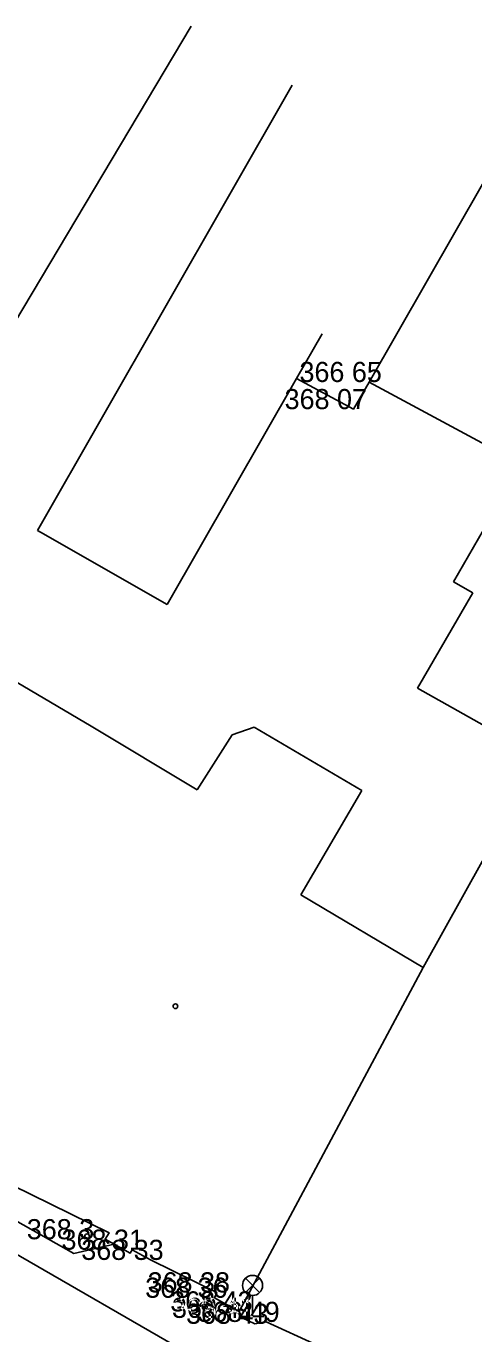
# Model space of a CAD drawing. Extents: x -688316 to -688024, y -973785 to -973591.
# Drawn here: x -688125.39 to -688108.72, y -973639.59 to -973590.87 of the extents above; entities that cross this region are included whole.
import ezdxf

# ---------------------------------------------------------------- set-up
doc = ezdxf.new("R2010")
doc.units = 0
for name, color, linetype in [('Vrstva 10', 7, 'Continuous'), ('Vrstva 3', 7, 'Continuous'), ('Vrstva 33', 7, 'Continuous'), ('Vrstva 5', 7, 'Continuous'), ('Vrstva 58', 7, 'Continuous'), ('Vrstva 7', 7, 'Continuous')]:
    doc.layers.add(name, color=color, linetype=linetype)

# ---------------------------------------------------------------- blocks, each defined once
blk = doc.blocks.new('B_NESP')
at = {"layer": 'Vrstva 58'}
blk.add_circle((0, 0), 0.875, dxfattribs=at)
blk = doc.blocks.new('LAO')
at = {"layer": 'Vrstva 33'}
for p, q in [((-2.65, 14.16), (2.65, 8.85)), ((-2.65, 8.85), (2.65, 14.16)), ((0, 0), (0, 7.75))]:
    blk.add_line(p, q, dxfattribs=at)
blk.add_circle((0, 11.5), 3.75, dxfattribs=at)

msp = doc.modelspace()

# ---------------------------------------------------------------- linework, layer by layer
at = {"layer": 'Vrstva 10'}
msp.add_line((-688128.13, -973635.26), (-688116.85, -973641.76), dxfattribs=at)
at = {"layer": 'Vrstva 5'}
for p, q in [((-688119.25, -973590.87), (-688128.07, -973605.69)), ((-688124.97, -973609.66), (-688115.48, -973593.07)), ((-688124.86, -973609.72), (-688124.97, -973609.66)), ((-688120.14, -973612.42), (-688124.86, -973609.72)), ((-688128.71, -973613.57), (-688122.97, -973616.95)), ((-688122.97, -973616.95), (-688119.02, -973619.32)), ((-688117.72, -973617.27), (-688116.9, -973616.99)), ((-688116.9, -973616.99), (-688112.89, -973619.35)), ((-688119.02, -973619.32), (-688117.72, -973617.27)), ((-688110.61, -973625.94), (-688106.58, -973618.7)), ((-688112.89, -973619.35), (-688115.16, -973623.24)), ((-688115.16, -973623.24), (-688110.61, -973625.94)), ((-688117.46, -973638.76), (-688110.61, -973625.94))]:
    msp.add_line(p, q, dxfattribs=at)
for points in [[(-688105.15, -973591.1), (-688112.62, -973604.13), (-688113.2, -973605.14), (-688115.32, -973604)], [(-688114.37, -973602.34), (-688115.32, -973604), (-688120.14, -973612.42)], [(-688127.39, -973632.92), (-688126.75, -973633.39), (-688126.83, -973633.52), (-688126.17, -973633.9), (-688125.91, -973634.05), (-688122.3, -973635.83), (-688122.45, -973636.07), (-688122.11, -973636.25), (-688121.52, -973636.59), (-688121.44, -973636.46), (-688120.76, -973636.84), (-688118.29, -973638.05), (-688118.38, -973638.25), (-688117.46, -973638.76), (-688117.34, -973639), (-688116.87, -973639.22), (-688116.45, -973639.15), (-688114.55, -973640.02), (-688114.81, -973640.46), (-688114.6, -973640.52), (-688114.18, -973640.39)], [(-688126.17, -973633.9), (-688125.79, -973635.37), (-688123.61, -973636.6), (-688122.11, -973636.25)]]:
    msp.add_lwpolyline(points, dxfattribs=at)
at = {"layer": 'Vrstva 7'}
for p, q in [((-688106.28, -973607.55), (-688112.62, -973604.13)), ((-688109.47, -973611.58), (-688107.46, -973608.06)), ((-688108.76, -973611.98), (-688109.47, -973611.58)), ((-688110.82, -973615.54), (-688108.76, -973611.98)), ((-688106.23, -973618.12), (-688110.82, -973615.54))]:
    msp.add_line(p, q, dxfattribs=at)

# ---------------------------------------------------------------- block references
at = {"layer": 'Vrstva 33', "xscale": 0.1, "yscale": 0.10000000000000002}
msp.add_blockref('LAO', (-688116.96, -973638.94), dxfattribs=at)
at = {"layer": 'Vrstva 58', "xscale": 0.1, "yscale": 0.10000000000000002}
for p in [(-688119.83, -973627.39), (-688119.83, -973627.39), (-688119.83, -973627.39), (-688119.83, -973627.39), (-688123.12, -973635.96), (-688123.12, -973635.96), (-688123.12, -973635.96), (-688123.12, -973635.96)]:
    msp.add_blockref('B_NESP', p, dxfattribs=at)

# ---------------------------------------------------------------- texts
at = {"layer": 'Vrstva 3'}
for s, p in [('366 65 ', (-688115.212, -973604.13)), ('366 65 ', (-688115.212, -973604.13)), ('366 65 ', (-688115.212, -973604.13)), ('366 65 ', (-688115.212, -973604.13)), ('366 65 ', (-688115.212, -973604.13)), ('366 65 ', (-688115.212, -973604.13)), ('366 65 ', (-688115.212, -973604.13)), ('368 07 ', (-688115.766, -973605.14)), ('368 07 ', (-688115.766, -973605.14)), ('368 07 ', (-688115.766, -973605.14)), ('368 07 ', (-688115.766, -973605.14)), ('368 07 ', (-688115.766, -973605.14)), ('368 07 ', (-688115.766, -973605.14)), ('368 07 ', (-688115.766, -973605.14)), ('368 3  ', (-688125.367, -973636.07)), ('368 3  ', (-688125.367, -973636.07)), ('368 3  ', (-688125.367, -973636.07)), ('368 3  ', (-688125.367, -973636.07)), ('368 3  ', (-688125.367, -973636.07)), ('368 3  ', (-688125.367, -973636.07)), ('368 3  ', (-688125.367, -973636.07)), ('368 31 ', (-688124.073, -973636.46)), ('368 31 ', (-688124.073, -973636.46)), ('368 31 ', (-688124.073, -973636.46)), ('368 31 ', (-688124.073, -973636.46)), ('368 31 ', (-688124.073, -973636.46)), ('368 31 ', (-688124.073, -973636.46)), ('368 31 ', (-688124.073, -973636.46)), ('368 33 ', (-688123.338, -973636.84)), ('368 33 ', (-688123.338, -973636.84)), ('368 33 ', (-688123.338, -973636.84)), ('368 33 ', (-688123.338, -973636.84)), ('368 33 ', (-688123.338, -973636.84)), ('368 33 ', (-688123.338, -973636.84)), ('368 33 ', (-688123.338, -973636.84)), ('368 36 ', (-688120.958, -973638.25)), ('368 36 ', (-688120.958, -973638.25)), ('368 36 ', (-688120.958, -973638.25)), ('368 36 ', (-688120.958, -973638.25)), ('368 36 ', (-688120.958, -973638.25)), ('368 36 ', (-688120.958, -973638.25)), ('368 36 ', (-688120.958, -973638.25)), ('368 38 ', (-688120.868, -973638.05)), ('368 38 ', (-688120.868, -973638.05)), ('368 38 ', (-688120.868, -973638.05)), ('368 38 ', (-688120.868, -973638.05)), ('368 38 ', (-688120.868, -973638.05)), ('368 38 ', (-688120.868, -973638.05)), ('368 38 ', (-688120.868, -973638.05)), ('368 43 ', (-688120.026, -973638.76)), ('368 43 ', (-688120.026, -973638.76)), ('368 43 ', (-688120.026, -973638.76)), ('368 43 ', (-688120.026, -973638.76)), ('368 43 ', (-688120.026, -973638.76)), ('368 43 ', (-688120.026, -973638.76)), ('368 43 ', (-688120.026, -973638.76)), ('368 41 ', (-688119.961, -973639)), ('368 41 ', (-688119.961, -973639)), ('368 41 ', (-688119.961, -973639)), ('368 41 ', (-688119.961, -973639)), ('368 41 ', (-688119.961, -973639)), ('368 41 ', (-688119.961, -973639)), ('368 41 ', (-688119.961, -973639)), ('368 43 ', (-688119.436, -973639.22)), ('368 43 ', (-688119.436, -973639.22)), ('368 43 ', (-688119.436, -973639.22)), ('368 43 ', (-688119.436, -973639.22)), ('368 43 ', (-688119.436, -973639.22)), ('368 43 ', (-688119.436, -973639.22)), ('368 43 ', (-688119.436, -973639.22)), ('368 49 ', (-688119.016, -973639.15)), ('368 49 ', (-688119.016, -973639.15)), ('368 49 ', (-688119.016, -973639.15)), ('368 49 ', (-688119.016, -973639.15)), ('368 49 ', (-688119.016, -973639.15)), ('368 49 ', (-688119.016, -973639.15)), ('368 49 ', (-688119.016, -973639.15))]:
    msp.add_text(s, height=0.75, dxfattribs=at).set_placement(p)

doc.saveas('drawing.dxf')
